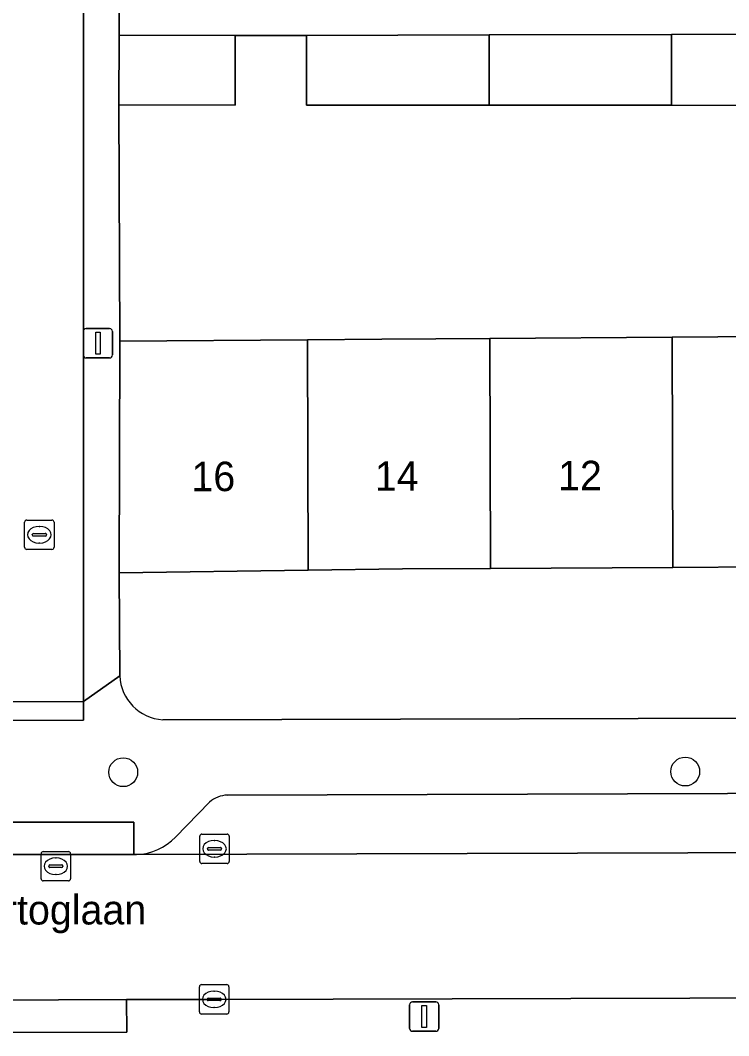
# Model space of a CAD drawing. Extents: x 160732 to 162107, y 387428 to 388479.
# Drawn here: x 161217.9 to 161241.95, y 387806.41 to 387840.87 of the extents above; entities that cross this region are included whole.
import ezdxf

# ---------------------------------------------------------------- set-up
doc = ezdxf.new("R2010")
doc.units = 0
for name, color, linetype in [('IMGEO_Boom', 7, 'Continuous'), ('IMGEO_Erf', 7, 'Continuous'), ('IMGEO_Kolk', 7, 'Continuous'), ('IMGEO_Lichtmast', 7, 'Continuous'), ('IMGEO_Openbare_ruimte_label', 7, 'Continuous'), ('IMGEO_Pand', 7, 'Continuous'), ('IMGEO_Pand_nummerreeks', 7, 'Continuous'), ('IMGEO_Parkeervlak_open', 7, 'Continuous'), ('IMGEO_Rijbaan_lokaal_open', 7, 'Continuous'), ('IMGEO_Rioolput', 7, 'Continuous'), ('IMGEO_Voetpad_open', 7, 'Continuous')]:
    doc.layers.add(name, color=color, linetype=linetype)

msp = doc.modelspace()

# ---------------------------------------------------------------- linework, layer by layer
at = {"layer": 'IMGEO_Boom'}
for centre in [(161221.394, 387815.347), (161240.479, 387815.369)]:
    msp.add_circle(centre, 0.489, dxfattribs=at)
at = {"layer": 'IMGEO_Erf'}
for points in [[(161246.207, 387837.978), (161240.014, 387837.98), (161233.823, 387837.983), (161227.612, 387837.985), (161227.612, 387840.349), (161225.197, 387840.349), (161225.19, 387837.985), (161221.248, 387837.998), (161221.281, 387829.974), (161227.651, 387830.02), (161230.176, 387830.039), (161233.842, 387830.065), (161240.033, 387830.11), (161246.225, 387830.155)], [(161271.155, 387822.478), (161264.814, 387822.442), (161258.623, 387822.406), (161252.432, 387822.371), (161246.243, 387822.336), (161240.052, 387822.3), (161233.861, 387822.265), (161230.879, 387822.248), (161227.67, 387822.204), (161221.256, 387822.117), (161221.274, 387818.618)], [(161222.736, 387817.131), (161271.169, 387817.264), (161271.155, 387822.478)]]:
    msp.add_lwpolyline(points, dxfattribs=at)
msp.add_arc((161222.832, 387818.687), 1.559, 182.5488, 266.4797, dxfattribs=at)
at = {"layer": 'IMGEO_Kolk'}
for p, q in [((161218.046, 387822.98), (161218.046, 387823.832)), ((161218.121, 387823.906), (161218.973, 387823.906)), ((161219.047, 387823.832), (161219.047, 387822.98)), ((161218.305, 387823.4), (161218.305, 387823.412)), ((161218.348, 387823.449), (161218.746, 387823.449)), ((161218.534, 387823.686), (161218.559, 387823.686)), ((161218.789, 387823.412), (161218.789, 387823.4)), ((161218.743, 387823.363), (161218.345, 387823.363)), ((161218.557, 387823.126), (161218.532, 387823.126)), ((161218.973, 387822.906), (161218.121, 387822.906)), ((161223.993, 387812.323), (161223.993, 387813.175)), ((161224.068, 387813.249), (161224.92, 387813.249)), ((161224.994, 387813.175), (161224.994, 387812.323)), ((161224.252, 387812.743), (161224.252, 387812.755)), ((161224.295, 387812.792), (161224.693, 387812.792)), ((161224.481, 387813.029), (161224.506, 387813.029)), ((161224.736, 387812.755), (161224.736, 387812.743)), ((161224.69, 387812.706), (161224.292, 387812.706)), ((161224.504, 387812.469), (161224.479, 387812.469)), ((161224.92, 387812.249), (161224.068, 387812.249)), ((161223.982, 387807.213), (161223.982, 387808.065)), ((161224.057, 387808.139), (161224.909, 387808.139)), ((161224.47, 387807.919), (161224.495, 387807.919)), ((161224.983, 387808.065), (161224.983, 387807.213)), ((161224.241, 387807.633), (161224.241, 387807.645)), ((161224.679, 387807.596), (161224.281, 387807.596)), ((161224.284, 387807.682), (161224.682, 387807.682)), ((161224.725, 387807.645), (161224.725, 387807.633)), ((161224.493, 387807.359), (161224.468, 387807.359)), ((161224.909, 387807.139), (161224.057, 387807.139))]:
    msp.add_line(p, q, dxfattribs=at)
for points in [[(161218.046, 387822.98), (161218.046, 387823.832)], [(161218.121, 387823.906), (161218.973, 387823.906)], [(161219.047, 387823.832), (161219.047, 387822.98)], [(161218.973, 387822.906), (161218.121, 387822.906)], [(161223.993, 387812.323), (161223.993, 387813.175)], [(161224.068, 387813.249), (161224.92, 387813.249)], [(161224.994, 387813.175), (161224.994, 387812.323)], [(161224.92, 387812.249), (161224.068, 387812.249)], [(161223.982, 387807.213), (161223.982, 387808.065)], [(161224.057, 387808.139), (161224.909, 387808.139)], [(161224.983, 387808.065), (161224.983, 387807.213)], [(161224.909, 387807.139), (161224.057, 387807.139)]]:
    msp.add_lwpolyline(points, dxfattribs=at)
for centre, radius, start, end in [((161218.123, 387823.83), 0.0765, 91.552, 178.448), ((161218.123, 387823.83), 0.0765, 91.552, 178.448), ((161218.971, 387823.83), 0.0765, 1.552, 88.448), ((161218.971, 387823.83), 0.0765, 1.552, 88.448), ((161218.345, 387823.409), 0.0403, 85.8775, 175.7526), ((161218.75, 387823.411), 0.0386, 1.7309, 96.639), ((161218.342, 387823.399), 0.0366, 178.938, 274.7102), ((161218.746, 387823.406), 0.043, 264.8664, 352.4533), ((161218.123, 387822.982), 0.0765, 181.552, 268.448), ((161218.123, 387822.982), 0.0765, 181.552, 268.448), ((161218.971, 387822.982), 0.0765, 271.552, 358.448), ((161218.971, 387822.982), 0.0765, 271.552, 358.448), ((161224.07, 387813.173), 0.0765, 91.552, 178.448), ((161224.07, 387813.173), 0.0765, 91.552, 178.448), ((161224.918, 387813.173), 0.0765, 1.552, 88.448), ((161224.918, 387813.173), 0.0765, 1.552, 88.448), ((161224.292, 387812.752), 0.0403, 85.8775, 175.7526), ((161224.289, 387812.742), 0.0366, 178.938, 274.7102), ((161224.693, 387812.749), 0.043, 264.8664, 352.4533), ((161224.697, 387812.754), 0.0386, 1.7309, 96.639), ((161224.07, 387812.325), 0.0765, 181.552, 268.448), ((161224.07, 387812.325), 0.0765, 181.552, 268.448), ((161224.918, 387812.325), 0.0765, 271.552, 358.448), ((161224.918, 387812.325), 0.0765, 271.552, 358.448), ((161224.059, 387808.063), 0.0765, 91.552, 178.448), ((161224.059, 387808.063), 0.0765, 91.552, 178.448), ((161224.907, 387808.063), 0.0765, 1.552, 88.448), ((161224.907, 387808.063), 0.0765, 1.552, 88.448), ((161224.281, 387807.642), 0.0403, 85.8775, 175.7526), ((161224.278, 387807.632), 0.0366, 178.938, 274.7102), ((161224.682, 387807.639), 0.043, 264.8664, 352.4533), ((161224.686, 387807.644), 0.0386, 1.7309, 96.639), ((161224.059, 387807.215), 0.0765, 181.552, 268.448), ((161224.059, 387807.215), 0.0765, 181.552, 268.448), ((161224.907, 387807.215), 0.0765, 271.552, 358.448), ((161224.907, 387807.215), 0.0765, 271.552, 358.448)]:
    msp.add_arc(centre, radius, start, end, dxfattribs=at)
for centre, major_axis, ratio, start_param, end_param in [((161218.533, 387823.406), (-0.387, 0.002), 0.722429, 4.712389, 7.853982), ((161218.558, 387823.406), (-0.39, 0.002), 0.717154, 1.570796, 4.712389), ((161224.48, 387812.749), (-0.387, 0.002), 0.722429, 4.712389, 7.853982), ((161224.505, 387812.749), (-0.39, 0.002), 0.717154, 1.570796, 4.712389), ((161224.469, 387807.639), (-0.387, 0.002), 0.722429, 4.712389, 7.853982), ((161224.494, 387807.639), (-0.39, 0.002), 0.717154, 1.570796, 4.712389)]:
    msp.add_ellipse(centre, major_axis=major_axis, ratio=ratio, start_param=start_param, end_param=end_param, dxfattribs=at)
at = {"layer": 'IMGEO_Lichtmast'}
for p, q in [((161220.04, 387829.507), (161220.04, 387830.307)), ((161220.04, 387830.307), (161220.04, 387829.507)), ((161220.14, 387830.407), (161220.93, 387830.407)), ((161220.93, 387830.407), (161220.14, 387830.407)), ((161221.03, 387830.307), (161221.03, 387829.507)), ((161221.03, 387829.507), (161221.03, 387830.307)), ((161220.93, 387829.407), (161220.14, 387829.407)), ((161220.14, 387829.407), (161220.93, 387829.407)), ((161231.117, 387806.655), (161231.117, 387807.455)), ((161231.117, 387807.455), (161231.117, 387806.655)), ((161231.217, 387807.555), (161232.007, 387807.555)), ((161232.007, 387807.555), (161231.217, 387807.555)), ((161232.107, 387807.455), (161232.107, 387806.655)), ((161232.107, 387806.655), (161232.107, 387807.455)), ((161232.007, 387806.555), (161231.217, 387806.555)), ((161231.217, 387806.555), (161232.007, 387806.555))]:
    msp.add_line(p, q, dxfattribs=at)
for points in [[(161220.46, 387830.282), (161220.61, 387830.282), (161220.61, 387829.532), (161220.46, 387829.532), (161220.46, 387830.282)], [(161231.537, 387807.43), (161231.687, 387807.43), (161231.687, 387806.68), (161231.537, 387806.68), (161231.537, 387807.43)]]:
    msp.add_lwpolyline(points, dxfattribs=at)
for centre, start, end in [((161220.14, 387830.307), 90, 180), ((161220.14, 387830.307), 90, 180), ((161220.93, 387830.307), 0, 90), ((161220.93, 387830.307), 360, 90), ((161220.14, 387829.507), 180, 270), ((161220.14, 387829.507), 180, 270), ((161220.93, 387829.507), 270, 0), ((161220.93, 387829.507), 270, 0), ((161231.217, 387807.455), 90, 180), ((161231.217, 387807.455), 90, 180), ((161232.007, 387807.455), 0, 90), ((161232.007, 387807.455), 360, 90), ((161231.217, 387806.655), 180, 270), ((161231.217, 387806.655), 180, 270), ((161232.007, 387806.655), 270, 0), ((161232.007, 387806.655), 270, 0)]:
    msp.add_arc(centre, 0.1, start, end, dxfattribs=at)
at = {"layer": 'IMGEO_Pand'}
for points in [[(161221.248, 387837.998), (161225.19, 387837.985), (161225.197, 387840.349), (161221.255, 387840.362)], [(161233.823, 387837.983), (161233.817, 387840.367), (161227.612, 387840.349), (161227.612, 387837.985)], [(161240.014, 387837.98), (161240.008, 387840.384), (161233.817, 387840.367), (161233.823, 387837.983)], [(161246.207, 387837.978), (161246.202, 387840.401), (161240.008, 387840.384), (161240.014, 387837.98)], [(161221.281, 387829.974), (161221.256, 387822.117), (161227.67, 387822.204), (161227.651, 387830.02)], [(161227.651, 387830.02), (161227.67, 387822.204), (161230.879, 387822.248), (161233.861, 387822.265), (161233.842, 387830.065), (161230.176, 387830.039)], [(161240.052, 387822.3), (161240.033, 387830.11), (161233.842, 387830.065), (161233.861, 387822.265)], [(161240.033, 387830.11), (161240.052, 387822.3), (161246.243, 387822.336), (161246.225, 387830.155)]]:
    msp.add_lwpolyline(points, close=True, dxfattribs=at)
at = {"layer": 'IMGEO_Parkeervlak_open'}
for points in [[(161286.088, 387814.773), (161224.922, 387814.571)], [(161224.326, 387814.335), (161223.173, 387813.146)], [(161221.844, 387812.557), (161289.232, 387812.758)]]:
    msp.add_lwpolyline(points, dxfattribs=at)
for centre, radius, start, end in [((161224.974, 387813.569), 1.004, 92.9787, 130.2258), ((161221.794, 387814.464), 1.907, 271.5013, 316.3036)]:
    msp.add_arc(centre, radius, start, end, dxfattribs=at)
at = {"layer": 'IMGEO_Rijbaan_lokaal_open'}
for points in [[(161216.995, 387840.302), (161217.013, 387817.741), (161220.039, 387817.747), (161220.046, 387848.238)], [(161256.61, 387807.719), (161280.924, 387807.785), (161286.933, 387807.801), (161292.574, 387807.805), (161292.568, 387812.753), (161289.472, 387812.767), (161289.232, 387812.758), (161221.844, 387812.557), (161221.753, 387812.557), (161215.604, 387812.56), (161200.337, 387812.505), (161200.286, 387807.545), (161214.578, 387807.602), (161221.503, 387807.631), (161224.483, 387807.637), (161244.672, 387807.689)]]:
    msp.add_lwpolyline(points, dxfattribs=at)
at = {"layer": 'IMGEO_Rioolput'}
for p, q in [((161218.604, 387811.731), (161218.604, 387812.583)), ((161218.679, 387812.657), (161219.531, 387812.657)), ((161219.092, 387812.437), (161219.117, 387812.437)), ((161219.605, 387812.583), (161219.605, 387811.731)), ((161218.863, 387812.151), (161218.863, 387812.163)), ((161219.301, 387812.114), (161218.903, 387812.114)), ((161218.906, 387812.2), (161219.304, 387812.2)), ((161219.347, 387812.163), (161219.347, 387812.151)), ((161219.115, 387811.877), (161219.09, 387811.877)), ((161219.531, 387811.657), (161218.679, 387811.657))]:
    msp.add_line(p, q, dxfattribs=at)
for points in [[(161218.604, 387811.731), (161218.604, 387812.583)], [(161218.679, 387812.657), (161219.531, 387812.657)], [(161219.605, 387812.583), (161219.605, 387811.731)], [(161219.531, 387811.657), (161218.679, 387811.657)]]:
    msp.add_lwpolyline(points, dxfattribs=at)
for centre, radius, start, end in [((161218.681, 387812.581), 0.0765, 91.552, 178.448), ((161218.681, 387812.581), 0.0765, 91.552, 178.448), ((161219.529, 387812.581), 0.0765, 1.552, 88.448), ((161219.529, 387812.581), 0.0765, 1.552, 88.448), ((161218.903, 387812.16), 0.0403, 85.8775, 175.7526), ((161218.9, 387812.15), 0.0366, 178.938, 274.7102), ((161219.304, 387812.157), 0.043, 264.8664, 352.4533), ((161219.308, 387812.162), 0.0386, 1.7309, 96.639), ((161218.681, 387811.733), 0.0765, 181.552, 268.448), ((161218.681, 387811.733), 0.0765, 181.552, 268.448), ((161219.529, 387811.733), 0.0765, 271.552, 358.448), ((161219.529, 387811.733), 0.0765, 271.552, 358.448)]:
    msp.add_arc(centre, radius, start, end, dxfattribs=at)
for centre, major_axis, ratio, start_param, end_param in [((161219.091, 387812.157), (-0.387, 0.002), 0.722429, 4.712389, 7.853982), ((161219.116, 387812.157), (-0.39, 0.002), 0.717154, 1.570796, 4.712389)]:
    msp.add_ellipse(centre, major_axis=major_axis, ratio=ratio, start_param=start_param, end_param=end_param, dxfattribs=at)
at = {"layer": 'IMGEO_Voetpad_open'}
for points in [[(161219.987, 387848.72), (161220.046, 387848.238), (161220.039, 387817.747), (161221.274, 387818.618), (161221.256, 387822.117), (161221.281, 387829.974), (161221.248, 387837.998), (161221.255, 387840.362), (161221.255, 387841.531), (161221.255, 387841.867), (161221.263, 387844.371), (161221.248, 387851.69), (161221.238, 387859.528)], [(161221.255, 387841.531), (161221.255, 387840.362), (161225.197, 387840.349), (161227.612, 387840.349), (161233.817, 387840.367), (161240.008, 387840.384), (161246.202, 387840.401), (161250.151, 387840.412), (161254.651, 387840.425), (161258.586, 387840.436), (161262.533, 387840.447), (161267.033, 387840.46), (161271.104, 387840.472), (161271.103, 387837.968), (161271.18, 387830.335), (161271.155, 387822.478), (161271.169, 387817.264), (161272.36, 387817.267)], [(161221.274, 387818.618), (161220.039, 387817.747), (161220.048, 387817.116), (161217.002, 387817.108), (161217.013, 387817.741), (161215.88, 387817.112), (161168.944, 387816.981)], [(161298.773, 387817.384), (161297.505, 387817.379), (161293.657, 387817.316), (161293.485, 387817.347), (161288.241, 387817.311), (161272.36, 387817.267), (161271.169, 387817.264), (161222.736, 387817.131)], [(161224.922, 387814.571), (161286.088, 387814.773)], [(161223.173, 387813.146), (161224.326, 387814.335)], [(161215.604, 387812.56), (161215.608, 387813.655), (161221.75, 387813.653), (161221.753, 387812.557), (161221.844, 387812.557)], [(161244.672, 387807.689), (161224.483, 387807.637), (161221.503, 387807.631), (161221.513, 387806.529), (161214.577, 387806.511), (161214.578, 387807.602), (161200.286, 387807.545), (161196.815, 387807.535), (161187.735, 387807.527), (161187.737, 387806.409), (161174.383, 387806.378), (161174.376, 387807.484), (161166.936, 387807.485), (161166.859, 387804.507), (161210.227, 387804.485), (161215.499, 387804.51), (161220.629, 387804.612), (161222.311, 387804.607), (161222.607, 387804.606), (161225.336, 387804.636), (161260.216, 387804.873), (161282.806, 387804.942), (161291.009, 387804.992)]]:
    msp.add_lwpolyline(points, dxfattribs=at)
for points in [[(161220.048, 387817.116), (161220.039, 387817.747), (161217.013, 387817.741), (161217.002, 387817.108)], [(161221.753, 387812.557), (161221.75, 387813.653), (161215.608, 387813.655), (161215.604, 387812.56)], [(161214.578, 387807.602), (161214.577, 387806.511), (161221.513, 387806.529), (161221.503, 387807.631)]]:
    msp.add_lwpolyline(points, close=True, dxfattribs=at)
for centre, radius, start, end in [((161222.832, 387818.687), 1.559, 182.5488, 266.4797), ((161224.974, 387813.569), 1.004, 92.9787, 130.2258), ((161221.794, 387814.464), 1.907, 271.5013, 316.3036)]:
    msp.add_arc(centre, radius, start, end, dxfattribs=at)

# ---------------------------------------------------------------- texts
at = {"layer": 'IMGEO_Openbare_ruimte_label'}
msp.add_text('Baarle Hertoglaan', height=1, rotation=0.0573, dxfattribs=at).set_placement((161211.397, 387810.172))
at = {"layer": 'IMGEO_Pand_nummerreeks'}
for s, p in [('16', (161223.711, 387824.884)), ('14', (161229.938, 387824.899)), ('12', (161236.162, 387824.914))]:
    msp.add_text(s, height=1, rotation=0.1369, dxfattribs=at).set_placement(p)

doc.saveas('drawing.dxf')
